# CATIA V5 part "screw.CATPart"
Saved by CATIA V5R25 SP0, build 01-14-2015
Part number: screw
Bounding box of the stored display mesh (mm): x -14.877 to 14.877, y -40 to 25, z 0 to 100
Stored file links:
  D:\screw.CATPart
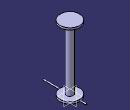
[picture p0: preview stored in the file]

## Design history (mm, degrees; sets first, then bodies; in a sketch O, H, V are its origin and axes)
Body1 (main body)
  Sketch1 on yz-plane, origin (0, 0, 0), H (0, 1, 0), V (0, 0, 1)
    line L1 (0, 0) -> (-15, 0)
    line L2 (-15, 0) -> (-15, 3)
    line L3 (-15, 3) -> (-5, 3)
    line L4 (-5, 3) -> (-5, 97)
    line L5 (-5, 97) -> (-15, 97)
    line L6 (-15, 97) -> (-15, 100)
    line L7 (-15, 100) -> (0, 100)
    point P7 (0, 100)
    axis line L8 (0, 0) -> (0, 100)
    distance L7 L1 = 100
    length L6 = 3
    length L2 = 3
    radius about axis L8 L6 = 15
    radius about axis L2 L8 = 15
    radius about axis L4 L8 = 5
    horizontal: L1 H, L3 H, L5 H, L7 H
    vertical: L2 V, L4 V, L6 V, L8 V
    coincidence: P7 V
  Shaft1: profile Sketch1, axis Sketch1.L8, angle 360
  Sketch2 on zx-plane, origin (0, 0, 0), H (-1, 0, 0), V (0, 0, 1)
    circle A1 centre (0, 1.5) radius 1
    point P1 (0, 1.5)
    radius A1 = 1
    distance P1 H = 1.5
    coincidence: P1 V
  Pad1: profile Sketch2, direction (0, 1, 0), length 25, opposite side length 40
